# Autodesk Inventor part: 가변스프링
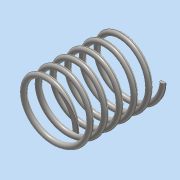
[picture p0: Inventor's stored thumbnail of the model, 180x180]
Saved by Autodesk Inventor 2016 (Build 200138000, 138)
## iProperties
Created: 2018-11
Part Number: 가변스프링
Material: 스테인레스 스틸
Document SubType Name: Modeling
Designer: 공506_39
Density: 8 g/cm^3
Appearance: 반연마
Mass: 84.1963 g
Surface Area: 106.449 cm^2
Volume: 10.5245 cm^3
Author: 공506_39
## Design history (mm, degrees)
sketch "스케치2"
  geometry: L1 (0, 0)-(22.5, 0); L2 (22.5, 0)-(22.5, 67.25); L3 (22.5, 67.25)-(0, 67.25); L4 (0, 67.25)-(0, 0); C1 r 2 at (22.5, 0)
  constraints: 8 end point, 2 parallel, 1 centre point, 1 coincident, 1 horizontal, 1 perpendicular
  dimensions: "d11" = 67.25 distance of L3.end L1.start (derived); "d12" = 45 diameter of L2 L4; "d13" = 4 diameter of C1
feature "코일2" sketch "스케치2" pitch "d14" = 10; turns "d16" = 6; dims "d15" = 67.25 (= d11), "d17" = 0, angle "d18" = 90 deg, angle "d19" = 90 deg, "d20" = 0, "d21" = 0
sketch "스케치3"
  geometry: L1 (67.25, 33.07)-(0, 33.07); L2 (0, 33.07)-(0, -33.07); L3 (0, -33.07)-(67.25, -33.07); L4 (67.25, -33.07)-(67.25, 33.07); 2 further points
  constraints: 8 end point, 2 parallel, 1 coincident, 1 horizontal, 1 midpoint, 1 perpendicular
  dimensions: "d22" = 67.25 distance of L2.end L3.end (= d11); "d23" = 66.1391 distance of L3.end L1.start
extrude "돌출1" sketch "스케치3" stored distance "d24" = 60; taper "d25" = 0 deg
node "솔리드2"
